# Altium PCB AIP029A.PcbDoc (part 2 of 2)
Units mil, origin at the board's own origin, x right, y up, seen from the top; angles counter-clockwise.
Board outline 1259.84 x 1259.84 mil, 4 copper layers (Top Layer, MidLayer1, MidLayer2, Bottom Layer), stack 40.8 mil thick; 91 components, 74 nets, 317 pads, 128 vias.
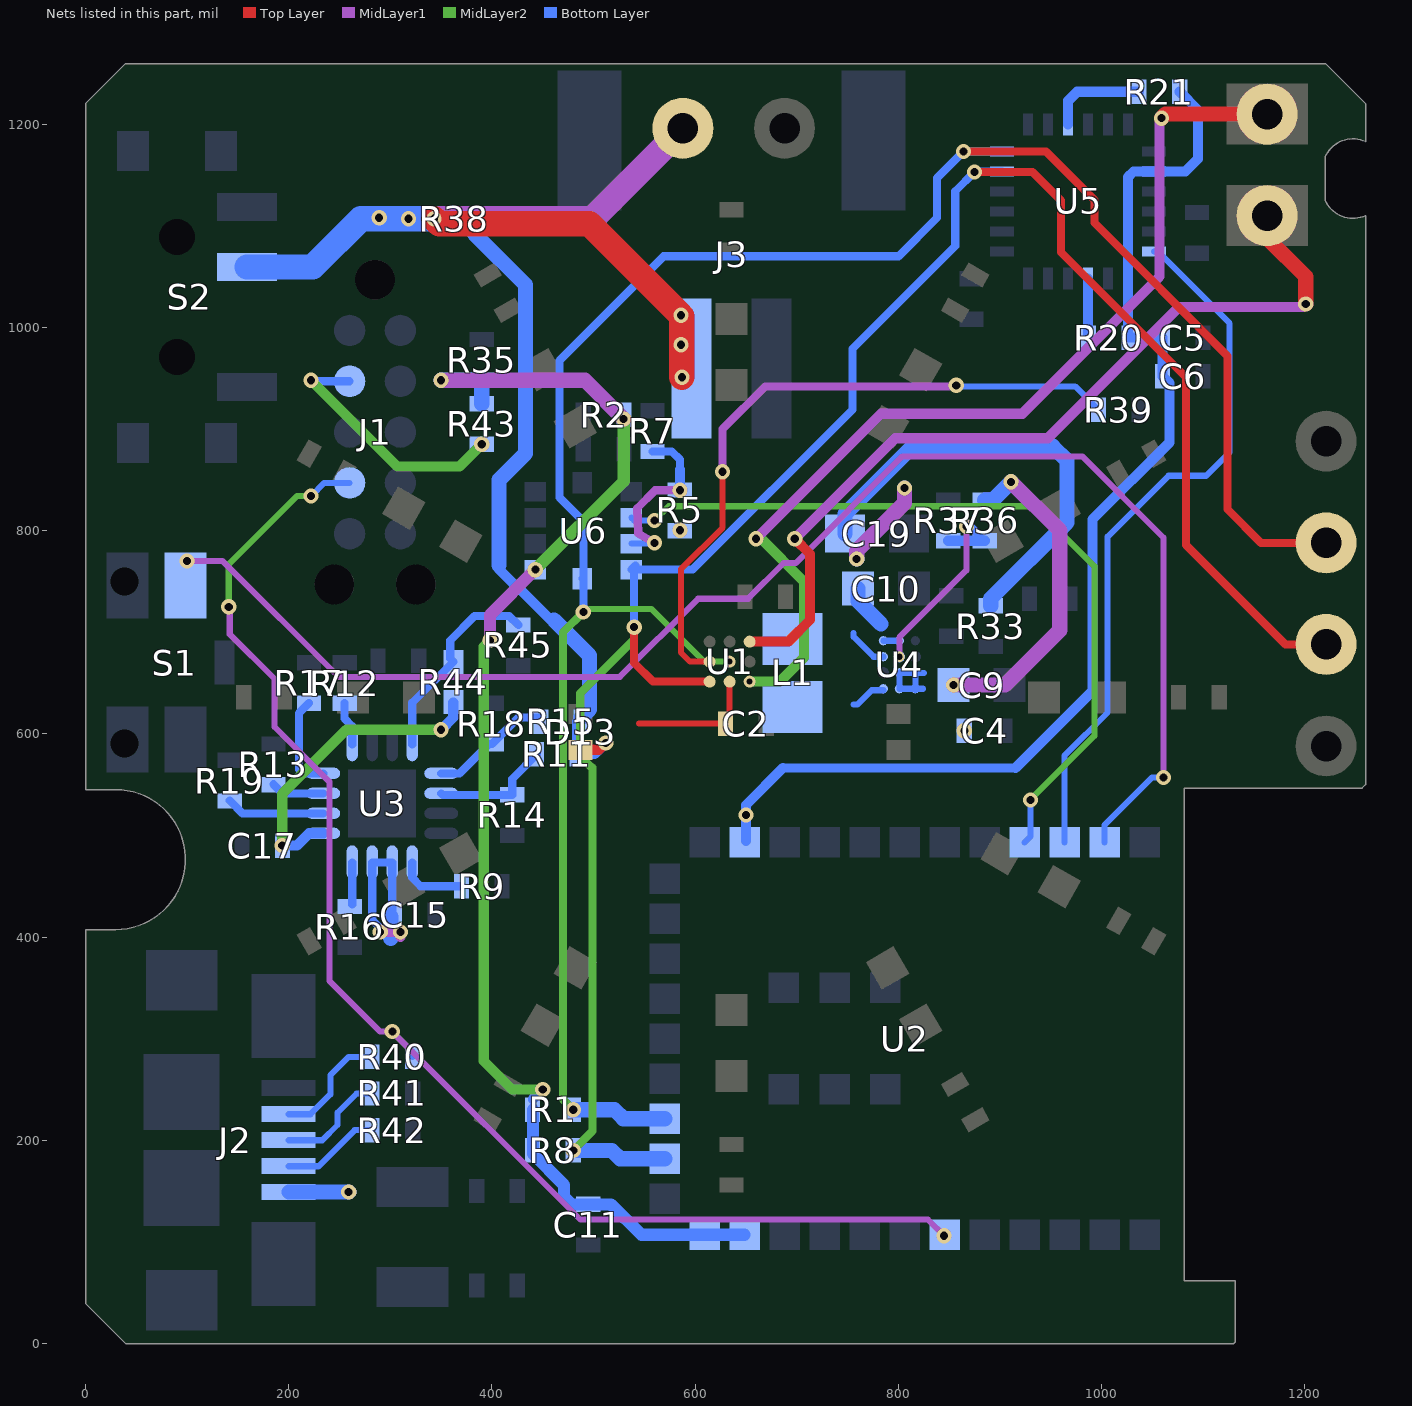
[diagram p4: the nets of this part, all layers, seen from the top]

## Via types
v1: diameter 15, hole 8, Top Layer to Bottom Layer, tented both sides, 116 vias
v2: diameter 19.68, hole 7.87, Top Layer to Bottom Layer, tented top, 5 vias
v3: diameter 10, hole 6, Top Layer to Bottom Layer, tented top, 3 vias
v4: diameter 10, hole 6, Top Layer to Bottom Layer, tented bottom, 3 vias
v5: diameter 15, hole 8, Top Layer to Bottom Layer, tented top, 1 vias

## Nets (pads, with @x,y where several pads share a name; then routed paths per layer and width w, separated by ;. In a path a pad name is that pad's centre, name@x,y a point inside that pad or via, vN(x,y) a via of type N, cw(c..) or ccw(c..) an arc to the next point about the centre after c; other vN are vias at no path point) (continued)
NetJ1_9: J1.9 R43.1 | length 249.3
  MidLayer2 w10: v1(222,948) 307,863 368,863 v1(390,885)
  Bottom Layer w8: v1@223,947 J1.9@259.95,947
NetJ2_2: J2.2 R42.1 | length 97.1
  Bottom Layer w6: J2.2@200,174.41 229.41,174.41 265,210 R42.1@282,210 R42.1@282.32,210
NetJ2_3: J2.3 R41.1 | length 108.4
  Bottom Layer w6: J2.3@200,200 233,200 248,215 248,227.08 266.92,246 R41.1@282,246 R41.1@282.32,246
NetJ2_4: J2.4 R40.1 | length 116.7
  Bottom Layer w6: J2.4@200,225.59 221.39,225.59 241,245.2 241,264 259,282 R40.1@282,282 R40.1@282.32,282
NetL1_1: L1.1 U4.A1 | length 35.1
  Bottom Layer w6: 756,628.75 759.75,628.75 773.87,642.87 U4.A1@785.25,642.87
NetL1_2: L1.2 U4.C1 | length 40.9
  Bottom Layer w6: 756,699 756,695.5 775.63,675.87 U4.C1@785.25,675.87
NetR5_1: R5.1 R7.2 U6.8 | length 175.2
  MidLayer1 w8: v1(560,788) 544,797.24 543,822 560.68,839.68 v1(585,839.68)
  Bottom Layer w6: U6.8@537.24,787.2 v1@559.2,787.2
  Bottom Layer w8: R7.2@558,878 577,878 585,870 585,860
  Bottom Layer w10: R5.1@585,840 585,860
  Bottom Layer w15: v1(585,839.68) R5.1@585,840
NetR9_1: R9.1 U3.9 | length 67.3
  Bottom Layer w8: U3.9@321.55,473.53 321.55,458.45 330,450 R9.1@370,450 R9.1@370.32,450
NetR11_1: R11.1 R14.2 U3.6 | length 121
  Bottom Layer w8: U3.6@350.09,541.44 351.85,539.69 420,539.69 R14.2@420,540 420,555.68 R11.1@444.32,580
NetR12_2: R12.2 U3.1 | length 43.7
  Bottom Layer w8: R12.2@255,630.31 R12.2@255,630 255,615 262.49,607.51 U3.1@262.49,589.67
NetR13_2: R13.2 U3.15 | length 52.6
  Bottom Layer w8: R13.2@185,550.31 193.87,541.44 U3.15@233.95,541.44
NetR15_1: R15.1 R18.2 U3.5 | length 121.1
  Bottom Layer w8: U3.5@350.09,561.13 368.13,561.13 397,590 R18.2@400,590 425.69,615.69 425.69,616 R15.1@448.32,616
NetR16_2: R16.2 U3.12 | length 41.4
  Bottom Layer w8: R16.2@262.49,432.18 U3.12@262.49,473.53
NetR17_2: R17.2 U3.16 | length 95
  Bottom Layer w8: R17.2@220,630.31 210,620.31 210,565 213.87,561.13 U3.16@233.95,561.13
NetR19_2: R19.2 U3.14 | length 97.1
  Bottom Layer w8: R19.2@142,534.31 154.56,521.76 U3.14@233.95,521.76
NetR20_2: R20.2 U5.15 | length 58.3
  Bottom Layer w10: U5.15@986.84,1048.21 986.84,990.16 R20.2@987,990
NetR21_1: R21.1 U5.3 | length 96.9
  Bottom Layer w10: U5.3@967.16,1199.79 967.16,1223.16 976,1232 R21.1@1037,1232
NetR36_1: R36.1 R37.2 U4.C2 | length 215.3
  MidLayer1 w6: v3(801,675.87) 801,695 867,761 v1(867,804)
  Bottom Layer w8: v1(867,804) 871,804 R36.1@885,790
  Bottom Layer w10: R37.2@849,790 R36.1@885,790
NetR39_1: R39.1 U1.B1 | length 665.9
  Top Layer w6: U1.B1@614.28,671.04 594.96,671.04 585.96,680.04 585.96,761.96 627,803 v1(627,858)
  MidLayer1 w8: v1(627,858) 627,900 669,942 v1@857,942
  Bottom Layer w6: v1@857,942 974,942 R39.1@997,919
  other v1: 857,943
NetR44_1: R44.1 R45.2 U3.4 | length 201
  Bottom Layer w8: U3.4@321.55,589.67 321.55,630.55 362,671 359,674 359,692 383,716 417,716 R45.2@426,707
OUT+: pad.0@1163,1110 U1.A3 | length 855.8
  Top Layer w10: U1.A3@653.65,690.72 691.72,690.72 713,712 713,777 v1(698,792)
  Top Layer w15: pad.0@1163,1110 1163,1088 1201,1050 v1(1201,1023)
  MidLayer1 w10: v1(698,792) 797,891 947,891 1076,1020 1198,1020 v1(1201,1023)
OUT-: pad.0@1163,1210 U1.C3 | length 968.9
  Top Layer w15: v1(1059,1206) 1063,1210 pad.0@1163,1210
  MidLayer1 w10: v1(660,792) 783,915 922,915 1057,1050 1057,1204 v1(1059,1206)
  MidLayer2 w10: v4(653.65,651.35) 683.35,651.35 707,675 707,750 665,792 v1(660,792)
P0.0: S1.2 U2.32 | length 1461.8
  MidLayer1 w6: v1(100,770) 135,770 249,656 526,656 603,733 652,733 687,768 699,768 804,873 981,873 1061,793 v1(1061,557)
  Bottom Layer w6: U2.32@1003.07,493.11 1003.07,510.44 1049.63,557 v1(1061,557)
P0.1: U2.31 U5.12 | length 703.3
  Bottom Layer w6: U2.31@963.7,493.11 963.7,578.7 1006,621 1006,794 1066,854 1103,854 1126,877 1126,1004 1055.21,1074.79 U5.12@1051.8,1074.79
P0.2: U2.30 U6.7 | length 787.5
  MidLayer2 w6: v1(560,810) 574,824 934,824 993,765 993,598 v1(930,535)
  Bottom Layer w6: U6.7@537.24,812.8 540.04,810 v1(560,810) ; U2.30@924.33,493.11 930,498.78 v1(930,535)
P1.1: C5.2 C6.1 R20.1 R21.2 U2.23 U5.8 U5.13 | length 1146.6
  Bottom Layer w9: 686.5,566.5 915.5,566.5
  Bottom Layer w10: U2.23@650,494.37 v1(650,520) 650,530 686.5,566.5 ; 915.5,566.5 991,642 991,811 1067,887 1067,945 C6.1@1060,952 C5.2@1060,990 R20.1@1027,990 1026.21,990.79 U5.13@1026.21,1048.21 1026.21,1148.21 1031.53,1153.53 U5.8@1051.8,1153.53 1082.53,1153.53 1095,1166 1095,1214 R21.2@1077,1232
REG_VDD: C10.1 C11.2 C19.1 R1.2 R2.2 R5.2 R8.2 R33.2 R35.2 R43.2 U2.11 U2.12 U4.D1 U4.D2 U6.1 | length 1917.7
  MidLayer1 w12: v1(398,692) 398,716.86 v1(442.76,761.61)
  MidLayer1 w15: v5(350,948) 491.69,948 v1(529.69,910) ; v1(759,772) 759,780 806,827 v1(806,842)
  MidLayer2 w10: v1(398,692) 392,686 392,278 420,250 v1(450,250)
  MidLayer2 w12: v1(442.76,761.61) 529.69,848.54 v1(529.69,910)
  Bottom Layer w6: U4.D1@785.25,691.62 U4.D2@801,691.62
  Bottom Layer w10: R1.2@440.31,240.31 v1(450,250)
  Bottom Layer w12: R1.2@440.31,230 440.31,186.69 471,156 471,144 478.31,136.69 517.31,136.69 547.11,106.89 U2.12@609.37,106.89 U2.11@648.74,106.89
  Bottom Layer w15: v5(350,948) 350.31,948.31 R35.2@390,948.31 ; R43.2@390,925 R35.2@390,948 ; C19.1@747.5,797 747.5,816.5 814,883 952,883 966,869 966,808 891,733 R33.2@891,726 ; C10.1@760.44,743 760.44,730.56 783,708
  other v1: 585,800.31
RST: J1.7 R40.2 U2.6 | length 1345.2
  MidLayer1 w6: v1(141,725) 142,724 142,698 186,654 186,607 240,553 240,357 290,307 v1(302,307) 487,122 829,122 v1(845,106)
  MidLayer2 w6: v1(141,725) 141,767 208,834 v1(222,834)
  Bottom Layer w6: v1(222,834) 235,847 J1.7@259.95,847 ; v1(302,307) 321.69,287.31 R40.2@321.69,282
SCL: pad.0@1221,688 R8.1 U1.C1 U2.14 U5.23 U6.9 | length 2079.5
  Top Layer w8: v1(540,705) 540,670 558.65,651.35 U1.C1@614.28,651.35 ; v1(875,1153) 932,1153 960,1125 960,1074 1083,951 1083,786 1181,688 pad.0@1221,688
  MidLayer2 w8: v1(480,190) 499,209 499,567 498,567 487,578 487,640 540,693 v1(540,705)
  Bottom Layer w8: v1(540,705) U6.9@540,758.86 ; U6.9@541.19,765.56 U6.9@537.24,761.61 597.61,761.61 755,919 755,979 856,1080 856,1134 v1(875,1153) ; v1@875,1153.53 U5.23@902.2,1153.53
  Bottom Layer w15: R8.1@479.68,190 v1(480,190) 517.98,190 526.09,181.89 U2.14@570,181.89
SDA: pad.0@1221,788 R1.1 U1.B2 U2.15 U5.24 U6.10 | length 2181.4
  Top Layer w4: U1.B2@632.9,671.04 v4(633.96,671.04)
  Top Layer w8: v1(864.21,1173.21) 945.21,1173.21 993,1125.42 993,1103 1124,972 1124,821 1157,788 pad.0@1221,788
  MidLayer2 w6: v1(490,720) 493,723 557,723 608.96,671.04 v4@632.9,671.04
  MidLayer2 w8: v1(480,230) 470,240 470,700 v1(490,720)
  Bottom Layer w8: U6.10@489.02,752.76 490,751.77 v1(490,720) ; U6.10@490,753.74 490,809.01 466.51,832.51 466.51,865.18 466.5,967.5 569,1070 800,1070 838,1108 838,1147 v1(864.21,1173.21) U5.24@902.2,1173.21
  Bottom Layer w15: R1.1@479.68,230 v1(480,230) 520.63,230 529.37,221.26 U2.15@570,221.26
VBAT: J3.1 pad.0@588,1196 R38.1 S2.2 | length 828
  Top Layer w25: v1(343,1107) 348,1102 496,1102 v1(586,1012) ; v1(587,951) v1@587,1011
  MidLayer1 w25: v1(343,1107) 499,1107 pad.0@588,1196
  Bottom Layer w25: S2.2@158.9,1059.53 223.53,1059.53 271,1107 v1(318,1107) v1(343,1107)
  other v1: 586,983 289,1108
VBQOUT: C2.1 C4.1 C9.1 C15.1 D13.1 R11.2 R15.2 R36.2 R38.2 U1.C2 U3.10 U3.11 U4.A2 U4.A3 U4.B2 U4.B3 | length 1399.5
  Top Layer w6: 545,610 C2.1@630,610 630.32,610 633.96,613.65 U1.C2@633.96,651.35
  Top Layer w10: D13.1@487,584.28 505.28,584.28 v1(512,591)
  MidLayer1 w10: v1(290,405) v1(310,405) v1@310,400
  MidLayer1 w15: v1(854.44,648) 905,648 959,702 959,800 v1(911,848)
  Bottom Layer w6: U4.B3@816.75,660 U4.A3@816.75,644.38 ; 824.38,644.38 U4.A3@816.75,644.38 ; 825,660 816.87,660 U4.B3@816.75,660.13 U4.B2@801,660.13 U4.A2@801,644.38 U4.A3@816.75,644.38
  Bottom Layer w8: 300.31,398.69 282.18,416.82 U3.11@282.18,473.53 U3.10@301.86,473.53 301.86,421.55 C15.1@300.31,420 ; U4.A3@816.75,644.38 U4.A3@817.07,644.05
  Bottom Layer w10: 407,766 407,762 425.03,743.97 426.03,743.97 458,712 461,712 ; R15.2@487.69,616 483.69,612 483.69,580 R11.2@484,580 501,580 v1(512,591)
  Bottom Layer w15: 300.31,398.69 C15.1@300.31,420 ; R38.2@383,1107 383,1092 433,1042 433,876 407,850 407,766 ; 461,712 496,677 496,624 R15.2@488,616 ; R36.2@885,830 893,830 v1(911,848)
  other v1: 865,603
VUSB: C17.1 J2.1 R44.2 U3.13 | length 369.4
  MidLayer2 w10: v1(193.68,490) 193.68,540.94 256.74,604 v1(350,604)
  Bottom Layer w10: v1(193.68,490) C17.1@194,490 208,490 220.07,502.07 U3.13@233.95,502.07 ; v1(350,604) 362,616 R44.2@362,631
  Bottom Layer w15: J2.1@200.18,149 v1(259,149)
pads on no net: J1. J1.5 J1.6 J1.8 J1.10 J3.M1 J3.M2 S1.1 S1.MH1 S1.MH2 S2.3 S2.MH-1 TP1.1 TP2.1 U2.1 U2.9 U2.10 U3.7 U5.2 U5.4 U5.5 U5.6 U5.7 U5.14 U5.16 U5.19 U5.21 U5.22 U6.2 U6.3 U6.6

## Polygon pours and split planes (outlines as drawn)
VUSB on MidLayer2 "MidLayer2-No Net" (solid, pour order 8): 272,525 272,36 40,36 40,381.88 52.21,393.81 64.42,405.73 137.68,405.73 137.68,477.29 186.53,525
REG_VDD on MidLayer2 "MidLayer2-No Net 1" (solid, remove dead copper, pour order 12): 420,960 420,540.88 650.33,540.88 650.33,481 1034.22,481 1034.22,660.62 1111,660.62 1111,960 420,960
GND on MidLayer2 "MidLayer1-No Net 1" (solid, remove dead copper, pour order 11): 1200,1230 30,1230 30,570 150,570 150,370 150,360 30,360 30,60 60,60 1050,60 1050,600 1170,600 1170,1113.84 1170,1200 1200,1200
VBQOUT on MidLayer1 "MidLayer1-No Net" (solid, remove dead copper, pour order 10): 898.31,702 898.31,571.21 520.26,571.21 509.61,561.15 509.61,420.3 509.61,395.15 493.64,380.06 482.99,370 280.65,370 270,370 270,460.55 301.95,490.73 314.8,502.87 419.09,502.87 419.09,651.7 472.34,702
GND on MidLayer1 "MidLayer1-No Net 1" (solid, remove dead copper, pour order 9): 1203,1229 30,1229 30,557.72 150.31,557.72 150.31,354.3 150.31,344.13 30,344.13 30,39 60.08,39 1052.62,39 1052.62,588.23 1172.92,588.23 1172.92,1110.86 1172.92,1198.49 1203,1198.49
GND on Top Layer "Top Layer-No Net" (solid, remove dead copper, pour order 14): 18,1227 18,568.65 111.06,568.65 107.35,564.93 107.35,389.1 18,389.1 18,30 524.34,30 1000.9,30 1000.9,269.4 1000.9,478.88 1000.9,628.5 1179.61,628.5 1179.61,1227
GND on Bottom Layer "Bottom Layer-No Net" (solid, remove dead copper, pour order 13): 30,1200 30,630 30,570 120,570 123.73,566.27 123.73,390 123.73,361.21 120,357.48 117.48,360 30,360 30,30 360,30 1050,30 1050,270 1050,448.76 1051.24,450 1050,451.24 1050,570 1170,570 1170,870 1170,930 1230,930 1230,1080 1140,1080 1140,1230 870,1230 600,1230 330,1230 120,1230 30,1230

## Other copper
Top Layer:
  rectangle net VBAT: 443.68,1156.68 588,1236.22
  rectangle net GND: 741,672 762,691
  rectangle net GND: 711.48,622.47 735,665
  rectangle net GND: 728,623 777,680
  region net NetD4_2: 1014.31,410.78 1019.99,420.62 961.24,454.54 955.56,444.7
  region net NetD3_2: 1008.3,641.55 1008.3,630.19 1076.13,630.19 1076.13,641.55
  region net NetD12_2: 641.5,1076.18 630.15,1076.18 630.15,1008.35 641.5,1008.35
  region net NetD9_2: 263.34,630.18 263.34,641.54 195.5,641.54 195.5,630.18
  rectangle net NetD6_2: 630.13,195.55 641.49,263.38
  region net NetD7_2: 411.23,257.44 421.07,251.76 454.99,310.5 445.15,316.18
  region net NetD10_2: 257.39,860.45 251.71,850.61 310.45,816.7 316.13,826.53
  region net NetD1_2: 860.4,1014.3 850.56,1019.98 816.65,961.23 826.48,955.55
  region net NetD8_2: 253.38,417.64 258.29,409.13 317.04,443.05 312.12,451.56
  region net NetD11_2: 420.86,1020.19 411.02,1014.51 444.94,955.76 454.77,961.44
  region net NetD2_2: 1020.14,850.83 1014.46,860.66 955.72,826.75 961.39,816.91
  region net NetD5_2: 850.78,251.54 860.62,257.22 826.7,315.97 816.86,310.29
  rectangle net VBQOUT: 526,567 643,614
  rectangle net VBQOUT: 475,567 526,587
  rectangle net VBQOUT: 501,567 526,600
  rectangle net GND: 109.88,870.5 127.62,888.24
  rectangle net GND: 190.3,861.9 197.5,869.2
  text ".Layer_Name" at 601,-833 h60
MidLayer1:
  text ".Layer_Name" at 622,-833 h60
MidLayer2:
  text ".Layer_Name" at 610,-845 h60
Bottom Layer:
  rectangle net GND: 167,639 178,652
  rectangle net GND: 894,592 925,650
  rectangle net NetL1_2: 705,687 759,710
  rectangle net GND: 756,660 771,669
  rectangle net GND: 756,651 771,660
  rectangle net VBQOUT: 824.38,639 860,663
  rectangle net VBQOUT: 858,591 874,665
  rectangle net NetL1_1: 705,609 759,632
  rectangle net GND: 732,639 759,681
  rectangle net REG_VDD: 773,691 801,717
  rectangle net REG_VDD: 728,738 769,813
  rectangle net GND: 1140,570 1230,620
  rectangle net GND: 917.2,664.1 936.8,682.8
  rectangle net GND: 111.1,886.3 128.31,901.5
  rectangle net GND: 147.3,614.3 154.4,622.7
  region net VBQOUT: 282.18,473.53 282,473.35 280,390 315,390 316,436 310,442 307,465 301.86,473.53
  region net NetC16_1: 301.86,589.67 282.18,589.67 282.18,640 302,640
  text ".Layer_Name" at 610,-845 h60

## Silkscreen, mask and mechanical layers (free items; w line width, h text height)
Top Overlay:
  circle w5: c635.83,635.66 r236.22
  lines w5: 510,525 765,525 ; 648.62,1190.63 cw(c635.83,635.66) 1190.8,648.45 1190.8,559.23 1190.31,558.75 1161.12,558.75 1076.09,558.75 1076.09,529.92 889.61,579.88 ccw(c635.83,635.66) 889.61,691.43 1152.14,761.78 cw(c635.83,635.66) 1161.9,559.91 ; 649.37,1190.63 623.03,1190.63 ccw(c635.83,635.66) 102.8,790.71 ccw(c268.16,734.17) 96.69,767.89 ccw(c635.83,635.66) 96.69,503.42 ccw(c330.32,553.8) 102.8,480.61 ccw(c635.83,635.66) 623.03,80.69 648.62,80.69 1074.73,80.69 1076.64,82.6 1076.64,269.16 ; 1076.64,269.16 1076.64,505.31 883.5,557.07 cw(c635.83,635.66) 827.73,460.46 1019.03,269.16 1076.64,269.16 ; 119.51,509.54 cw(c635.83,635.66) 119.51,761.78 382.04,691.43 ccw(c635.83,635.66) 382.04,579.88 119.51,509.54 ; 125.62,486.72 ccw(c635.83,635.66) 251.74,268.28 443.93,460.46 cw(c635.83,635.66) 388.15,557.07 125.62,486.72 ; 125.62,784.59 cw(c635.83,635.66) 251.74,1003.04 443.93,810.85 ccw(c635.83,635.66) 388.15,714.25 125.62,784.59 ; 268.45,251.57 ccw(c635.83,635.66) 486.89,125.45 557.24,387.98 cw(c635.83,635.66) 460.63,443.76 268.45,251.57 ; 268.45,1019.74 cw(c635.83,635.66) 486.89,1145.86 557.24,883.33 ccw(c635.83,635.66) 460.63,827.56 268.45,1019.74 ; 509.71,119.34 ccw(c635.83,635.66) 761.95,119.34 691.6,381.87 cw(c635.83,635.66) 580.05,381.87 509.71,119.34 ; 509.71,1151.97 cw(c635.83,635.66) 761.95,1151.97 691.6,889.44 ccw(c635.83,635.66) 580.05,889.44 509.71,1151.97 ; 714.42,387.98 ccw(c635.83,635.66) 811.02,443.76 1003.21,251.57 cw(c635.83,635.66) 784.76,125.45 714.42,387.98 ; 714.42,883.33 cw(c635.83,635.66) 811.02,827.56 1003.21,1019.74 ccw(c635.83,635.66) 784.76,1145.86 714.42,883.33 ; 827.73,810.85 cw(c635.83,635.66) 883.5,714.25 1146.03,784.59 ccw(c635.83,635.66) 1019.91,1003.04 827.73,810.85
  lines w7: 587,596 595,588 693,588 699,594 699,747 619,747 604,747 587,730 587,596
  text "OUT-" at 1004,1186 h30
  text "+" at 455,1165 h80
  text "-" at 760,1160 h80
  text "XII" at 535,1105 h40
  text "OUT+" at 1004,1097 h30
  text "I" at 800,1055 h40
  text "XI" at 322,996 h40
  text "II" at 978,903 h40
  text "X" at 193.87,785.27 h40
  text "III" at 1039.79,675.03 h40
  text "IX" at 143,552 h40
  text "DRV2605" at 520,540 h35
  text "HAPTICS" at 505,470 h42
  text "IV" at 998.05,465.13 h40
  text "VIII" at 208.15,341.65 h40
  text "V" at 904.55,240.08 h40
  text "VII" at 410,178.38 h40
  text "VI" at 669.63,167.44 h40
  text "DRV2605EVM-BT" at 387,21 h35
  text "Top Overlay" at 622,-833 h60
Bottom Overlay:
  lines w5: 249.64,325.7 398.6,325.7 ; 367,681 380.97,694.97 380.97,701.83 ; 380,1090 385,1085 390,1085 399.98,1075.02 ; 461.19,699 562,699 ; 511.23,261.7 511.23,456.8 ; 575,878 587,878 601.98,863.02 ; 710,559 845,559 ; 836,937 951,937
  text "+" at 615,1085 h80
  text "-" at 710,1085 h80
  text "-" at 750,942 h50
  text "IMU3000" at 955,942 h35
  text "+" at 560,940 h50
  text "TI" at 1090,918 h80 r90
  text "TRG" at 1165,851 h35 r270
  text "SDA" at 1166,761 h35 r270
  text "KXTJ9" at 559.67,705 h35
  text "SCL" at 1164,663 h35 r270
  text "TPS63051" at 855,565 h35
  text "GND" at 1161.9,559.91 h35 r270
  text "CC2541- BLE" at 500.32,455.54 h35 r90
  text "BQ24232" at 394.69,330 h35
  text "AIP029 Rev.A" at 937,19 h28
  text "Bottom Overlay" at 664,-836 h60
Top Solder:
  text "T" at 36,105 h170
  text ".Layer_Name" at 601,-833 h60
Bottom Solder:
  text ".Layer_Name" at 601,-833 h60
M1 Board Outline:
  lines w5: 0,39.28 0,407.4 29.53,407.4 ccw(c29.53,476.29) 29.53,545.19 0,545.19 0,1220.39 39.37,1259.76 1220.47,1259.76 1259.84,1220.39 1259.84,1183 ccw(c1247.53,1155.44) 1219.97,1167.75 1219.97,1125.29 ccw(c1247.53,1137.6) 1259.84,1110.04 1259.84,1099.84 1259.84,550 1256.44,546.6 1086.6,546.6 1081.6,546.6 1081.6,61.6 1126.4,61.6 1131.6,61.6 1131.6,11.6 1131.6,6.51 1131.6,1.44 1130.08,-0.09 1019.91,-0.09 39.37,-0.09 0,39.28
M3 3D STEP Top:
  lines w1: 0,0 0,1259.84 1324.92,1259.84 1324.92,1229.84 1324.92,1189.84 1324.92,0
M9 Title Sheet:
  drawing of 57 lines, arcs and shapes, not listed
  text "1" at 739.84,8036.5 h70
  text "2" at 3235.5,8036.5 h70
  text "3" at 5724.84,8036.5 h70
  text "4" at 8231.51,8036.5 h70
  text "5" at 10730.5,8036.5 h70
  text "6" at 13235.5,8036.5 h70
  text "A" at -416.5,6893.5 h70
  text "A" at 14383.5,6893.5 h70
  text "B" at -416.5,4513.5 h70
  text "B" at 14383.5,4513.5 h70
  text "C" at -416.5,2138.5 h70
  text "C" at 14383.5,2138.5 h70
  text "PROJECT TITLE:" at 11343.5,277.5 h45
  text ".PRJ_Number" at 11393.5,144.17 h70
  text "DESIGNED FOR:" at 11343.5,-23.5 h45
  text "Public" at 11393.5,-163.5 h70
  text "D" at -416.5,-231.5 h70
  text "D" at 14383.5,-231.5 h70
  text "FILE NAME:" at 11343.5,-323.5 h45
  text ".Pcb_File_Name_No_Path" at 11393.5,-443.5 h70
  text "Texas Instruments (TI) and/or its licensors do not warrant the accuracy or completeness of this specification" at 6374,-605.34 h45
  text "ENGINEER:" at 11343.5,-613.5 h45
  text "LAYOUT BY:" at 12848.5,-613.5 h45
  text "or any information contained therein. TI and/or its licensors do not warrant that this design will meet" at 6329.01,-718 h45
  text "Gautham Ramachandran" at 11393.5,-768.49 h70
  text "Gautham Ramachandran" at 12899,-768.49 h70
  text "the specifications, will be suitable for your application or fit for any particular purpose, or will operate in" at 6329.01,-830.67 h45
  text "ALTIUM DESIGNER VERSION:" at 12848.5,-923.5 h45
  text "an implementation. TI and/or its licensors do not warrant that the design is production worthy. You should" at 6329.01,-943.33 h45
  text "completely validate and test your design implementation to confirm the system functionality for your application." at 6374,-1056 h45
  text "Altium 2010" at 12899,-1056.83 h70
  text "1" at 739.84,-1263.5 h70
  text "2" at 3235.5,-1263.5 h70
  text "3" at 5724.84,-1263.5 h70
  text "4" at 8231.51,-1263.5 h70
  text "5" at 10730.5,-1263.5 h70
  text "6" at 13235.5,-1263.5 h70
M10 Fab Notes:
  drawing of 211 lines, arcs and shapes, not listed
  text "DESIGN INFORMATION" at 12323.02,6944 h60
  text "(REFER ALSO ARRAY/PANEL PROFILING INFORMATION)" at 11961.46,6782.29 h60
  text "BOARD SIZE" at 11275.46,6778 h60
  text "1259.882 MIL" at 12415,6660 h60
  text "1259.882 MIL" at 11625,6655 h60
  text "X" at 12243.46,6650.18 h60
  text "Number of Layers :" at 11678.46,6453 h60
  text "4" at 12773.27,6443 h60
  text "MIN. TRACK WIDTH:" at 11678.46,6314 h60
  text "4" at 12774.7,6314 h60
  text "MIL" at 12929.46,6314 h60
  text "MIN. CLEARANCE:" at 11678.46,6182 h60
  text "3" at 12774.7,6182 h60
  text "MIL" at 12929.46,6182 h60
  text "0.05mm (2MIL)" at 12373.46,5908.29 h60
  text "MINIMUM ANNULAR RING" at 11349.23,5904 h60
  text "EXTERNAL" at 13081.46,5904 h60
  text "PER" at 11549.23,5786 h60
  text "IPC-D-275 CLASS 2 LEVEL C" at 11769.23,5786 h60
  text "MIL, HOLES" at 13257.46,5673.71 h60
  text "+/-" at 12865,5673 h60
  text "+/-" at 13719,5673 h60
  text "REGISTRATION TOLERANCES:" at 11349.23,5668 h60
  text "METAL" at 12549,5668 h60
  text "5" at 13125.2,5668 h60
  text "3" at 13958.2,5668 h60
  text "MIL" at 14074.46,5668 h60
  text "MATERIAL:" at 11274.46,5458.54 h60
  text "FR-4 High Tg" at 12260.9,5318.21 h60
  text "FR-408" at 11695.46,5309.64 h60
  text "X" at 12107.46,5309.64 h60
  text "OTHER" at 13183.46,5309.64 h60
  text "31 MIL" at 13650,5155 h60
  text "62 MIL (1.6mm) +/-10%" at 12015.56,5146.92 h60
  text "THICKNESS:" at 11349.23,5142.64 h60
  text "OTHER" at 13300.46,5142.64 h60
  text "X" at 13175,5135 h60
  text "TOLERANCE:" at 11349.23,4984.64 h60
  text "X" at 12188.53,4984.64 h60
  text "ANSI IPC-6012 TYPE 3 CLASS 2" at 12375.48,4984.64 h60
  text "OTHER +/-" at 12375.46,4828.64 h60
  text "BOW & TWIST:" at 11349.23,4671.64 h60
  text "X" at 12188.53,4671.64 h60
  text "ANSI IPC-6012 TYPE 3 CLASS 2" at 12375.48,4671.64 h60
  text "OTHER +/-" at 12375.46,4513.13 h60
  text "COPPER THICKNESS (FINISHED):" at 11274.46,4377.64 h60
  text "1.4MIL (1oz)" at 12154.46,4224.92 h60
  text "2MIL (1.4oz)" at 12921.46,4224.92 h60
  text "2.8MIL (2oz)" at 13648.46,4224.92 h60
  text "OUTER:" at 11631.46,4220.64 h60
  text "X" at 12026,4220 h60
  text "1.4MIL (1oz)" at 12154.46,4067.92 h60
  text "2.8MIL (2oz)" at 12921.46,4067.92 h60
  text "N/A" at 13648,4068.29 h60
  text "INNER SIGNAL:" at 11342.38,4063.64 h60
  text "X" at 12027.42,4063.64 h60
  text "DRILLING:" at 11274.46,3924.64 h60
  text "REFERENCE:" at 11349.23,3807.64 h60
  text "X" at 11997.46,3807.64 h60
  text "AS SHOWN" at 12184.46,3807.64 h60
  text "X" at 12898.46,3807.64 h60
  text "NC_DRILL FILES" at 13035.46,3807.64 h60
  text "PTH MIN COPPER THICKNESS:" at 11349.23,3649.64 h60
  text "X" at 12699.46,3649.64 h60
  text "1MIL" at 12836.46,3649.64 h60
  text "OTHER" at 13333.46,3649.64 h60
  text "BOARD FINISH:" at 11274.46,3490.64 h60
  text "SILKSCREEN:" at 11429.68,3372.64 h60
  text "X" at 12378.46,3372.64 h60
  text "TOP" at 12504.46,3372.64 h60
  text "X" at 12888.46,3372.64 h60
  text "BOTTOM" at 13015.46,3372.64 h60
  text "SILKSCREEN COLOR:" at 11429.68,3205.64 h60
  text "X" at 12377.42,3205.64 h60
  text "WHITE" at 12504.46,3205.64 h60
  text "OTHER" at 13015.46,3205.64 h60
  text "SOLDER RESIST COLOR:" at 11429.68,3035.64 h60
  text "BLACK" at 13720,2880 h60
  text "X" at 13098.51,2878.64 h60
  text "GREEN" at 12124.46,2876.44 h60
  text "BLUE" at 12715.46,2876.44 h60
  text "OTHER" at 13253.46,2876.44 h60
  text "IMMERSION GOLD (ENIG)" at 12335.46,2687.92 h60
  text "ENEPIG" at 13673,2684.64 h60
  text "SURFACE FINISH:" at 11274.46,2683.64 h60
  text "X" at 12148.51,2683.64 h60
  text "IMM. TIN/SILVER OR EQUIV" at 11604,2526.64 h60
  text "OTHER" at 13035.46,2526.64 h60
  text "ARRAY/PANEL:" at 11274.46,2347.64 h60
  text "CUT AND TRIM PER MECH LAYER 1" at 12335.46,2343.35 h60
  text "N.C. ROUTE" at 12335.46,2191.64 h60
  text "X" at 13014.46,2191.64 h60
  text "V. SCORE" at 13201.46,2191.64 h60
  text "CERTIFICATION:" at 11274.46,2054.64 h60
  text "MATERIALS AND WORKMANSHIP FOR ALL PCBS" at 11999.46,2054.64 h60
  text "TO MEET OR EXCEED THE REQUIREMENTS OF:" at 11999.46,1956.64 h60
  text "X" at 11625.96,1820.13 h60
  text "ANSI IPC-A-600F CLASS ->" at 11764.96,1820.13 h60
  text "X" at 13404.02,1820.13 h60
  text "2" at 13522.96,1820.14 h60
  text "1" at 13207.96,1818.64 h60
  text "3" at 13876.96,1818.64 h60
  text "X" at 11628.02,1660.64 h60
  text "UL 94V-0" at 11764.96,1660.64 h60
  text "X" at 12440.02,1660.64 h60
  text "RoHS" at 12576.96,1660.64 h60
  text "OTHER" at 13221.36,1660.64 h60
  text "PER ORDER" at 13618.42,1660.64 h60
  text "ADDITIONAL REQUIREMENTS:" at 11274.46,1519.64 h60
  text "MICROSECTION:" at 11349.23,1404.64 h60
  text "YES" at 12254.96,1404.64 h60
  text "REQUIRED" at 13116.46,1248.49 h60
  text "BARE BOARD ELEC. TEST:" at 11349.23,1245.64 h60
  text "NONE" at 12654.96,1245.64 h60
  text "X" at 12989.46,1245.64 h60
  text "PER ORDER" at 13708.46,1245.64 h60
  text "MANUFACTURER'S UL:" at 11349.23,1088.64 h60
  text "RAIL" at 12514.96,1084.35 h60
  text "METAL" at 13006.77,1084.35 h60
  text "X" at 13382,1084 h60
  text "SILK" at 13518.46,1084.35 h60
M11 Gerber Information:
  lines w10: -277,-920.17 6323,-920.17 ; -277,-716.83 6325,-716.83 ; -277,-513.5 -277,-1123.5 3728,-1123.5 6325,-1123.5 6325,-513.5 -276.5,-513.5 -276.5,-1123.5 1299,-1123.5 ; 2188,-1123.5 2188,-513.5 ; 3455,-716.83 3455,-513.5 ; 4295,-716.83 4295,-513.5 ; 4917,-1130 4917,-927.17
  text "ALL ARTWORK VIEWED FROM TOP SIDE" at -213.5,-645.67 h60
  text "BOARD #:" at 2263,-645.67 h60
  text "AIP029" at 2808.5,-645.67 h60
  text "REV:" at 3653,-645.67 h60
  text "A" at 3944.5,-645.67 h60
  text "SVN REV:" at 4491,-645.67 h60
  text "LAYER NAME =" at -213.5,-848.49 h60
  text ".plot_File_Name" at 611.49,-1046.19 h60
  text "PLOT NAME =" at -213.5,-1054.34 h60
  text "GENERATED    :" at 2265,-1054.34 h60
  text "5/21/2014" at 3134.5,-1054.34 h60
  text "18:51" at 3863.5,-1054.34 h60
  text "TEXAS INSTRUMENTS" at 5128,-1054.34 h60
M12 Stackup:
  lines w8: 7410,7405.25 11040,7405.25 ; 7410,7552.65 11040,7552.65 ; 7350,6463 ccw(c7398,6463) 7398,6415 11052,6415 ccw(c11052,6463) 11100,6463 11100,7682 ccw(c11052,7682) 11052,7730 7398,7730 ccw(c7398,7682) 7350,7682 7350,6463
  text "Layer Stack Up Detail for: AIP029A.PcbDoc" at 7410,7590.92 h68
  text "Layer" at 7410,7497.65 h34
  text "Gerber" at 8683.74,7497.65 h34
  text "Copper" at 9491.49,7497.65 h34
  text "Dielectric" at 10354.76,7497.65 h34
  text "Name" at 7410,7429.65 h34
  text "Document" at 8683.74,7429.65 h34
  text "Thickness" at 9491.49,7429.65 h34
  text "Material" at 10354.76,7429.65 h34
  text "Top Solder Mask" at 7410,7332.76 h48
  text "(.GTS)" at 8683.74,7332.76 h48
  text "Solder Resist" at 10354.76,7332.76 h48
  text "Top Layer" at 7410,7195.78 h48
  text "(.GTL)" at 8683.74,7195.78 h48
  text "1.4mil" at 9491.49,7195.78 h48
  text "FR-4" at 10354.76,7127.29 h48
  text "MidLayer1" at 7410,7058.8 h48
  text "(.G1)" at 8683.74,7058.8 h48
  text "1.4mil" at 9491.49,7058.8 h48
  text "FR-4" at 10354.76,6990.31 h48
  text "MidLayer2" at 7410,6921.82 h48
  text "(.G2)" at 8683.74,6921.82 h48
  text "1.4mil" at 9491.49,6921.82 h48
  text "FR-4" at 10354.76,6853.33 h48
  text "Bottom Layer" at 7410,6784.84 h48
  text "(.GBL)" at 8683.74,6784.84 h48
  text "1.4mil" at 9491.49,6784.84 h48
  text "Bottom Solder Mask" at 7410,6647.87 h48
  text "(.GBS)" at 8683.74,6647.87 h48
  text "Solder Resist" at 10354.76,6647.87 h48
Drill Drawing:
  text "ALL VIAS TO BE FILLED AND PLATED SHUT." at 43.5,2008.5 h60
  text ".legend" at 2590.5,272.5 h60
  text "Drill Table" at 2615.5,87.5 h60

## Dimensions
39.37,-0.09 to 39.37,1259.76 on M2 Board Dimensions
1259.84,1220.39 to 0,1220.39 on M2 Board Dimensions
